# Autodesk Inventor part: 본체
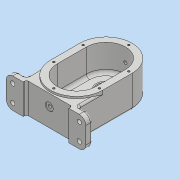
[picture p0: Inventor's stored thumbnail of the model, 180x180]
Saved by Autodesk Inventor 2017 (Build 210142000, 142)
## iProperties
Part Number: 본체
Material: 일반
Document SubType Name: Modeling
Designer: MRC
Density: 1 g/cm^3
Appearance: 기본값
Author: MRC
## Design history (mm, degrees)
sketch "스케치1"
  geometry: L1 (0, 0)-(0, -87); L2 (-40, 0)-(-40, -82); L3 (40, -82)-(40, 0); L4 (-40, -82)-(-61, -82); L5 (-61, -82)-(-61, -92); L6 (-61, -92)-(-35, -92); L7 (-35, -92)-(-35, -87); L8 (-35, -87)-(35, -87); L9 (35, -87)-(35, -92); L10 (35, -92)-(61, -92); L11 (61, -92)-(61, -82); L12 (61, -82)-(40, -82); A1 r 40 centre (0, 0) between (40, 0) and (-40, 0); 1 further point
  constraints: 26 end point, 5 perpendicular, 3 horizontal, 2 midpoint, 2 parallel, 2 point on circle, 2 point on line, 2 tangent, 2 vertical, 1 centre point
  dimensions: "d0" = 40 radius of A1; "d1" = 10 distance of L10.end L11.end; "d2" = 92 distance from line of L10 L1.start; "d3" = 5 distance of L8.end L9.end; "d4" = 70 distance of L7.end L8.end; "d5" = 122 distance between parallel lines of L11 L5; "d6" = 61 distance from line of point (0, -43.5) L5
extrude "돌출1" new body sketch "스케치1" distance "d7" = 46; taper "d8" = 0 deg
sketch "스케치2"
  geometry: L1 (0, 0)-(0, -45); L2 (-40, 0)-(-40, -45); L3 (40, -45)-(40, 0); A1 r 40 centre (0, 0) between (40, 0) and (-40, 0); A2 r 40 centre (0, -45) between (-40, -45) and (40, -45); A3 r 40 centre (0, 0) between (40, 0) and (-40, 0) reference; 1 further point
  constraints: 8 end point, 4 point on circle, 4 tangent, 2 centre point, 1 concentric, 1 midpoint, 1 parallel, 1 vertical
  dimensions: "d9" = 45 distance of L1.start L1.end
extrude "돌출2" join sketch "스케치2" distance "d10" = 3; taper "d11" = 0 deg
sketch "스케치3"
  geometry: L1 (0, 0)-(0, -45); L2 (-26, 0)-(-26, -45); L3 (26, -45)-(26, 0); A1 r 26 centre (0, 0) between (26, 0) and (-26, 0); A2 r 26 centre (0, -45) between (-26, -45) and (26, -45); 1 further point
  constraints: 8 end point, 4 point on circle, 4 tangent, 2 centre point, 1 midpoint, 1 parallel, 1 vertical
  dimensions: "d12" = 26 radius of A1; "d13" = 45 distance of L1.start L1.end
extrude "돌출3" join sketch "스케치3" distance "d14" = 11; taper "d15" = 0 deg
sketch "스케치4"
  geometry: L1 (-26, -45)-(-26, 0) reference; L2 (-26, -30)-(26, -30); L3 (26, 0)-(26, -45) reference; L4 (-26, 0)-(-26, -45) reference; L5 (26, -45)-(26, 0) reference; L6 (-26, -30)-(-26, 0); L7 (26, -30)-(26, 0); A1 r 26 centre (0, -45) between (-26, -45) and (26, -45) reference; A2 r 26 centre (0, 0) between (26, 0) and (-26, 0) reference; A3 r 26 centre (0, 0) between (26, 0) and (-26, 0); 1 further point
  constraints: 6 end point, 2 point on circle, 2 point on line, 1 centre point, 1 coincident, 1 collinear, 1 horizontal, 1 vertical
  dimensions: "d16" = 30 distance from line of L2 point (0, 0)
extrude "돌출4" cut sketch "스케치4" distance "d17" = 3; taper "d18" = 0 deg
sketch "스케치5"
  geometry: L1 (0, 0)-(0, -45); L2 (-30, 0)-(-30, -45); L3 (30, -45)-(30, 0); A1 r 30 centre (0, 0) between (30, 0) and (-30, 0); A2 r 30 centre (0, -45) between (-30, -45) and (30, -45); 1 further point
  constraints: 8 end point, 4 point on circle, 4 tangent, 2 centre point, 1 midpoint, 1 parallel, 1 vertical
  dimensions: "d19" = 45 distance of L1.start L1.end; "d20" = 30 radius of A1
extrude "돌출5" cut sketch "스케치5" distance "d21" = 41; taper "d22" = 0 deg
hole "구멍1" diameter "d25" = 20; stored, may be unused: countersink angle "d29" = 90 deg, drill point angle "d31" = 0 deg; dims "d23" = 10, "d24" = 10, "d26" = 6, "d27" = 28, "d28" = 8, "d30" = 12
hole "구멍2" diameter "d34" = 22; stored, may be unused: countersink angle "d38" = 90 deg, drill point angle "d40" = 0 deg; dims "d32" = 10, "d33" = 10, "d35" = 6, "d36" = 28, "d37" = 8, "d39" = 100
sketch "스케치6"
  geometry: C1 r 14 at (0, 0); 1 further point
  constraints: 1 centre point, 1 coincident
  dimensions: "d41" = 28 diameter of C1
extrude "돌출6" cut sketch "스케치6" distance "d42" = 4; taper "d43" = 0 deg
fillet "모깎기1" dims "d44" = 10
sketch "스케치7"
  geometry: L1 (-21, 36)-(-21, 10) reference; L2 (0, 0)-(-11, 0) reference; L3 (0, 46)-(0, 0) reference; L4 (0, 46)-(-11, 46) reference; L5 (91, 46)-(80, 46) reference; L6 (80, 46)-(80, 0) reference; L7 (91, 0)-(80, 0) reference; L8 (101, 36)-(101, 10) reference; A1 r 10 centre (-11, 36) between (-11, 46) and (-21, 36) reference; A2 r 10 centre (-11, 10) between (-21, 10) and (-11, 0) reference; A3 r 10 centre (91, 36) between (101, 36) and (91, 46) reference; A4 r 10 centre (91, 10) between (91, 0) and (101, 10) reference; 1 further point
hole "구멍3" sketch "스케치7" at (-11, 36), (-11, 10), (91, 36), (91, 10) diameter "d45" = 6.6; stored, may be unused: countersink angle "d49" = 90 deg, drill point angle "d51" = 0 deg; dims "d46" = 6, "d47" = 11, "d48" = 2, "d50" = 10
sketch "스케치8"
  geometry: L1 (0, 0)-(0, -45); L2 (-35, 0)-(-35, -45); L3 (35, -45)-(35, 0); C1 r 10 at (0, -45) reference; A1 r 35 centre (0, 0) between (35, 0) and (-35, 0); A2 r 35 centre (0, -45) between (-35, -45) and (35, -45); 7 further points
  constraints: 8 end point, 6 point on circle, 4 coincident, 4 tangent, 2 centre point, 1 midpoint, 1 parallel, 1 vertical
  dimensions: "d52" = 70 diameter of A2
hole "구멍4" sketch "스케치8" at (0, 35), (-35, 0), (35, 0), (35, -45), (-35, -45), (0, -80) diameter "d53" = 3.242; stored, may be unused: countersink angle "d57" = 90 deg, drill point angle "d59" = 118 deg; dims "d54" = 8, "d55" = 11, "d56" = 2, "d58" = 10
sketch "스케치9"
  geometry: L1 (75, 49)-(-5, 49) reference; L2 (0, 0)-(70, 0) reference; 3 further points
  constraints: 1 midpoint, 1 vertical alignment
  dimensions: "d60" = 21 distance from line of point (35, 28) L1
hole "구멍5" sketch "스케치9" at (35, 28) diameter "d61" = 4.917; stored, may be unused: countersink angle "d65" = 90 deg, drill point angle "d67" = 0 deg; dims "d62" = 12, "d63" = 12, "d64" = 1, "d66" = 17.1
node "작업 평면1"
sketch "스케치10"
  geometry: L1 (5, 49)-(-75, 49) reference; C1 r 6 at (-35, 28); 1 further point
  constraints: 1 centre point, 1 vertical alignment
  dimensions: "d69" = 12 diameter of C1; "d70" = 21 distance from line of L1 C1.centre
extrude "돌출7" join sketch "스케치10" stored distance "d71" = 4; taper "d72" = 0 deg
hole "구멍6" diameter "d75" = 4.917; stored, may be unused: countersink angle "d79" = 90 deg, drill point angle "d81" = 0 deg; dims "d73" = 10, "d74" = 10, "d76" = 20, "d77" = 12, "d78" = 1, "d80" = 20
chamfer "모따기1" distance "d82" = 1; stored, may be unused: second distance "d83" = 2, angle "d84" = 45 deg
fillet "모깎기2" dims "d85" = 5
fillet "모깎기3" dims "d86" = 3
fillet "모깎기4" dims "d87" = 3
fillet "모깎기5" dims "d88" = 0.3
sketch "스케치11"
  geometry: 2 further points
  constraints: 1 vertical alignment
  dimensions: "d89" = 20 distance of point (0, 0) point (0, 20)
hole "구멍7" sketch "스케치11" at (0, 20) diameter "d90" = 3.242; stored, may be unused: countersink angle "d94" = 90 deg, drill point angle "d96" = 118 deg; dims "d91" = 8, "d92" = 12, "d93" = 1, "d95" = 10
sketch "스케치12"
  geometry: L1 (51, -92)-(35, -92) reference; L2 (-35, -92)-(-51, -92) reference; A1 r 29 centre (0, -45) between (-29, -45) and (29, -45) reference; 3 further points
  constraints: 1 point on circle, 1 vertical alignment, 1 other
  dimensions: "d102" = 12 distance from line of L2 point (0, -80)
feature "엠보싱1" sketch "스케치12" dims "d0" = 40, "d1" = 10, "d2" = 92, "d3" = 5, "d4" = 70, "d5" = 122, "d6" = 61, "d9" = 45, "d100" = 0.5, "d101" = 0
fillet "모깎기6" dims "d103" = 3
node "솔리드1"
pattern_circular "원형 패턴1" dims angle "d98" = 360 deg
node "투영된 루프1"
node "투영된 루프2"
node "투영된 루프3"
other parameters: "d68" = -135
